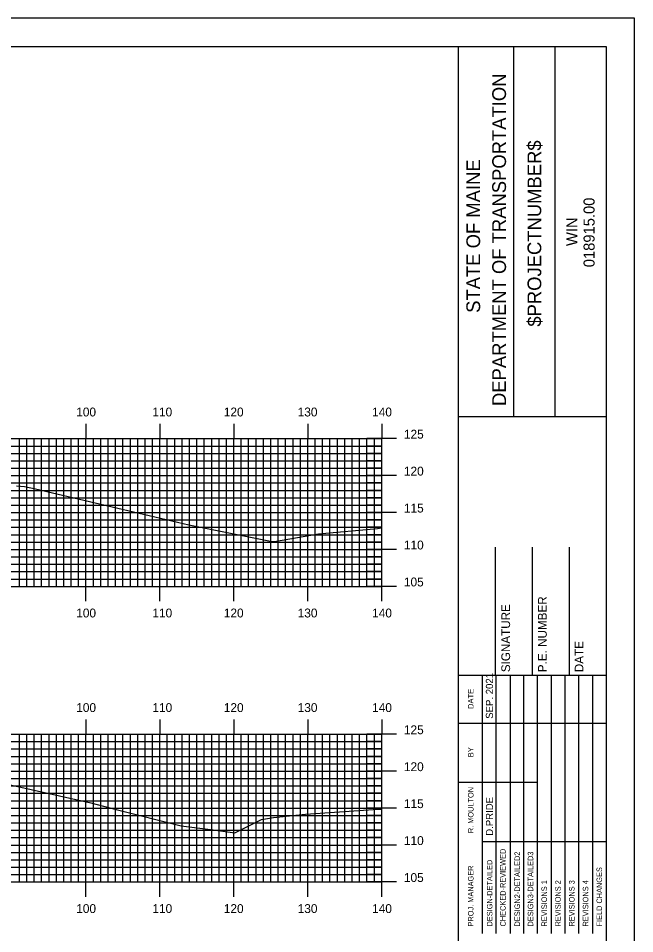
# Model space of a CAD drawing. Extents: x 855074 to 855418, y 366605 to 366825.
# Drawn here: x 855330.9 to 855414.3, y 366701.1 to 366824.9 of the extents above; entities that cross this region are included whole.
import ezdxf

# ---------------------------------------------------------------- set-up
doc = ezdxf.new("R2010")
doc.units = 0
for name, color, linetype in [('BORDER', 7, 'Continuous'), ('H_V ANNOTATION', 7, 'Continuous'), ('MAJOR', 7, 'Continuous'), ('MINOR', 7, 'Continuous'), ('PLOT BOUNDARY', 7, 'Continuous'), ('S_Roadway_Centerline', 7, 'Continuous')]:
    doc.layers.add(name, color=color, linetype=linetype)

msp = doc.modelspace()

# ---------------------------------------------------------------- linework, layer by layer
at = {"layer": 'BORDER'}
for p, q in [((855390.47, 366611.06), (855390.47, 366821.06)), ((855397.93, 366771.05), (855397.93, 366821.05)), ((855403.52, 366771.05), (855403.52, 366821.05)), ((855390.47, 366771.04), (855410.47, 366771.04)), ((855395.47, 366736.06), (855395.47, 366753.36)), ((855400.47, 366736.06), (855400.47, 366753.36)), ((855405.47, 366736.06), (855405.47, 366753.36)), ((855390.47, 366736.06), (855410.47, 366736.06))]:
    msp.add_line(p, q, dxfattribs=at)
msp.add_lwpolyline([(855090.47, 366611.06), (855410.47, 366611.06), (855410.47, 366821.06), (855090.47, 366821.06)], close=True, dxfattribs=at)
for points in [[(855393.7, 366729.56), (855393.7, 366736.06)], [(855395.56, 366701.07), (855395.56, 366736.06)], [(855397.43, 366736.06), (855397.43, 366701.07)], [(855399.29, 366701.07), (855399.29, 366736.06)], [(855401.15, 366701.07), (855401.15, 366736.06)], [(855403.02, 366701.07), (855403.02, 366736.06)], [(855404.88, 366701.07), (855404.88, 366736.06)], [(855406.74, 366701.07), (855406.74, 366736.06)], [(855408.61, 366701.07), (855408.61, 366736.06)], [(855393.7, 366701.07), (855393.7, 366734.65)], [(855390.47, 366729.56), (855410.47, 366729.56)], [(855390.47, 366721.56), (855393.7, 366721.56)], [(855393.7, 366721.56), (855401.15, 366721.56)], [(855393.7, 366713.56), (855410.47, 366713.56)]]:
    msp.add_lwpolyline(points, dxfattribs=at)
at = {"layer": 'MAJOR'}
for p, q in [((855340.07, 366770.06), (855340.07, 366768.06)), ((855350.07, 366770.06), (855350.07, 366768.06)), ((855360.07, 366770.06), (855360.07, 366768.06)), ((855370.07, 366770.06), (855370.07, 366768.06)), ((855380.07, 366770.06), (855380.07, 366768.06)), ((855100.07, 366768.06), (855380.07, 366768.06)), ((855100.07, 366768.06), (855380.07, 366768.06)), ((855340.07, 366748.06), (855340.07, 366768.06)), ((855350.07, 366748.06), (855350.07, 366768.06)), ((855360.07, 366748.06), (855360.07, 366768.06)), ((855370.07, 366748.06), (855370.07, 366768.06)), ((855382.07, 366768.06), (855378.07, 366768.06)), ((855380.07, 366748.06), (855380.07, 366768.06)), ((855380.07, 366748.06), (855380.07, 366768.06)), ((855100.07, 366763.06), (855380.07, 366763.06)), ((855382.07, 366763.06), (855378.07, 366763.06)), ((855100.07, 366758.06), (855380.07, 366758.06)), ((855382.07, 366758.06), (855378.07, 366758.06)), ((855100.07, 366753.06), (855380.07, 366753.06)), ((855382.07, 366753.06), (855378.07, 366753.06)), ((855100.07, 366748.06), (855380.07, 366748.06)), ((855100.07, 366748.06), (855380.07, 366748.06)), ((855340.07, 366746.05), (855340.07, 366748.06)), ((855350.07, 366746.05), (855350.07, 366748.06)), ((855360.07, 366746.05), (855360.07, 366748.06)), ((855370.07, 366746.05), (855370.07, 366748.06)), ((855382.07, 366748.06), (855378.07, 366748.06)), ((855380.07, 366746.05), (855380.07, 366748.06)), ((855340.07, 366730.06), (855340.07, 366728.06)), ((855350.07, 366730.06), (855350.07, 366728.06)), ((855360.07, 366730.06), (855360.07, 366728.06)), ((855370.07, 366730.06), (855370.07, 366728.06)), ((855380.07, 366730.06), (855380.07, 366728.06)), ((855100.07, 366728.06), (855380.07, 366728.06)), ((855100.07, 366728.06), (855380.07, 366728.06)), ((855340.07, 366708.06), (855340.07, 366728.06)), ((855350.07, 366708.06), (855350.07, 366728.06)), ((855360.07, 366708.06), (855360.07, 366728.06)), ((855370.07, 366708.06), (855370.07, 366728.06)), ((855382.07, 366728.06), (855378.07, 366728.06)), ((855380.07, 366708.06), (855380.07, 366728.06)), ((855380.07, 366708.06), (855380.07, 366728.06)), ((855100.07, 366723.06), (855380.07, 366723.06)), ((855382.07, 366723.06), (855378.07, 366723.06)), ((855100.07, 366718.06), (855380.07, 366718.06)), ((855382.07, 366718.06), (855378.07, 366718.06)), ((855100.07, 366713.06), (855380.07, 366713.06)), ((855382.07, 366713.06), (855378.07, 366713.06)), ((855100.07, 366708.06), (855380.07, 366708.06)), ((855100.07, 366708.06), (855380.07, 366708.06)), ((855340.07, 366706.05), (855340.07, 366708.06)), ((855350.07, 366706.05), (855350.07, 366708.06)), ((855360.07, 366706.05), (855360.07, 366708.06)), ((855370.07, 366706.05), (855370.07, 366708.06)), ((855382.07, 366708.06), (855378.07, 366708.06)), ((855380.07, 366706.05), (855380.07, 366708.06))]:
    msp.add_line(p, q, dxfattribs=at)
at = {"layer": 'MINOR'}
for p, q in [((855331.07, 366748.06), (855331.07, 366768.06)), ((855332.07, 366748.06), (855332.07, 366768.06)), ((855333.07, 366748.06), (855333.07, 366768.06)), ((855334.07, 366748.06), (855334.07, 366768.06)), ((855335.07, 366748.06), (855335.07, 366768.06)), ((855336.07, 366748.06), (855336.07, 366768.06)), ((855337.07, 366748.06), (855337.07, 366768.06)), ((855338.07, 366748.06), (855338.07, 366768.06)), ((855339.07, 366748.06), (855339.07, 366768.06)), ((855341.07, 366748.06), (855341.07, 366768.06)), ((855342.07, 366748.06), (855342.07, 366768.06)), ((855343.07, 366748.06), (855343.07, 366768.06)), ((855344.07, 366748.06), (855344.07, 366768.06)), ((855345.07, 366748.06), (855345.07, 366768.06)), ((855346.07, 366748.06), (855346.07, 366768.06)), ((855347.07, 366748.06), (855347.07, 366768.06)), ((855348.07, 366748.06), (855348.07, 366768.06)), ((855349.07, 366748.06), (855349.07, 366768.06)), ((855351.07, 366748.06), (855351.07, 366768.06)), ((855352.07, 366748.06), (855352.07, 366768.06)), ((855353.07, 366748.06), (855353.07, 366768.06)), ((855354.07, 366748.06), (855354.07, 366768.06)), ((855355.07, 366748.06), (855355.07, 366768.06)), ((855356.07, 366748.06), (855356.07, 366768.06)), ((855357.07, 366748.06), (855357.07, 366768.06)), ((855358.07, 366748.06), (855358.07, 366768.06)), ((855359.07, 366748.06), (855359.07, 366768.06)), ((855361.07, 366748.06), (855361.07, 366768.06)), ((855362.07, 366748.06), (855362.07, 366768.06)), ((855363.07, 366748.06), (855363.07, 366768.06)), ((855364.07, 366748.06), (855364.07, 366768.06)), ((855365.07, 366748.06), (855365.07, 366768.06)), ((855366.07, 366748.06), (855366.07, 366768.06)), ((855367.07, 366748.06), (855367.07, 366768.06)), ((855368.07, 366748.06), (855368.07, 366768.06)), ((855369.07, 366748.06), (855369.07, 366768.06)), ((855371.07, 366748.06), (855371.07, 366768.06)), ((855372.07, 366748.06), (855372.07, 366768.06)), ((855373.07, 366748.06), (855373.07, 366768.06)), ((855374.07, 366748.06), (855374.07, 366768.06)), ((855375.07, 366748.06), (855375.07, 366768.06)), ((855376.07, 366748.06), (855376.07, 366768.06)), ((855377.07, 366748.06), (855377.07, 366768.06)), ((855378.07, 366748.06), (855378.07, 366768.06)), ((855379.07, 366748.06), (855379.07, 366768.06)), ((855100.07, 366767.06), (855380.07, 366767.06)), ((855380.07, 366767.06), (855378.07, 366767.06)), ((855100.07, 366766.06), (855380.07, 366766.06)), ((855380.07, 366766.06), (855378.07, 366766.06)), ((855100.07, 366765.06), (855380.07, 366765.06)), ((855100.07, 366764.06), (855380.07, 366764.06)), ((855380.07, 366765.06), (855378.07, 366765.06)), ((855380.07, 366764.06), (855378.07, 366764.06)), ((855100.07, 366762.06), (855380.07, 366762.06)), ((855380.07, 366762.06), (855378.07, 366762.06)), ((855100.07, 366761.06), (855380.07, 366761.06)), ((855380.07, 366761.06), (855378.07, 366761.06)), ((855100.07, 366760.06), (855380.07, 366760.06)), ((855100.07, 366759.06), (855380.07, 366759.06)), ((855380.07, 366760.06), (855378.07, 366760.06)), ((855380.07, 366759.06), (855378.07, 366759.06)), ((855100.07, 366757.06), (855380.07, 366757.06)), ((855380.07, 366757.06), (855378.07, 366757.06)), ((855100.07, 366756.06), (855380.07, 366756.06)), ((855380.07, 366756.06), (855378.07, 366756.06)), ((855100.07, 366755.06), (855380.07, 366755.06)), ((855100.07, 366754.06), (855380.07, 366754.06)), ((855380.07, 366755.06), (855378.07, 366755.06)), ((855380.07, 366754.06), (855378.07, 366754.06)), ((855100.07, 366752.06), (855380.07, 366752.06)), ((855380.07, 366752.06), (855378.07, 366752.06)), ((855100.07, 366751.06), (855380.07, 366751.06)), ((855380.07, 366751.06), (855378.07, 366751.06)), ((855100.07, 366750.06), (855380.07, 366750.06)), ((855100.07, 366749.06), (855380.07, 366749.06)), ((855380.07, 366750.06), (855378.07, 366750.06)), ((855380.07, 366749.06), (855378.07, 366749.06)), ((855331.07, 366708.06), (855331.07, 366728.06)), ((855332.07, 366708.06), (855332.07, 366728.06)), ((855333.07, 366708.06), (855333.07, 366728.06)), ((855334.07, 366708.06), (855334.07, 366728.06)), ((855335.07, 366708.06), (855335.07, 366728.06)), ((855336.07, 366708.06), (855336.07, 366728.06)), ((855337.07, 366708.06), (855337.07, 366728.06)), ((855338.07, 366708.06), (855338.07, 366728.06)), ((855339.07, 366708.06), (855339.07, 366728.06)), ((855341.07, 366708.06), (855341.07, 366728.06)), ((855342.07, 366708.06), (855342.07, 366728.06)), ((855343.07, 366708.06), (855343.07, 366728.06)), ((855344.07, 366708.06), (855344.07, 366728.06)), ((855345.07, 366708.06), (855345.07, 366728.06)), ((855346.07, 366708.06), (855346.07, 366728.06)), ((855347.07, 366708.06), (855347.07, 366728.06)), ((855348.07, 366708.06), (855348.07, 366728.06)), ((855349.07, 366708.06), (855349.07, 366728.06)), ((855351.07, 366708.06), (855351.07, 366728.06)), ((855352.07, 366708.06), (855352.07, 366728.06)), ((855353.07, 366708.06), (855353.07, 366728.06)), ((855354.07, 366708.06), (855354.07, 366728.06)), ((855355.07, 366708.06), (855355.07, 366728.06)), ((855356.07, 366708.06), (855356.07, 366728.06)), ((855357.07, 366708.06), (855357.07, 366728.06)), ((855358.07, 366708.06), (855358.07, 366728.06)), ((855359.07, 366708.06), (855359.07, 366728.06)), ((855361.07, 366708.06), (855361.07, 366728.06)), ((855362.07, 366708.06), (855362.07, 366728.06)), ((855363.07, 366708.06), (855363.07, 366728.06)), ((855364.07, 366708.06), (855364.07, 366728.06)), ((855365.07, 366708.06), (855365.07, 366728.06)), ((855366.07, 366708.06), (855366.07, 366728.06)), ((855367.07, 366708.06), (855367.07, 366728.06)), ((855368.07, 366708.06), (855368.07, 366728.06)), ((855369.07, 366708.06), (855369.07, 366728.06)), ((855371.07, 366708.06), (855371.07, 366728.06)), ((855372.07, 366708.06), (855372.07, 366728.06)), ((855373.07, 366708.06), (855373.07, 366728.06)), ((855374.07, 366708.06), (855374.07, 366728.06)), ((855375.07, 366708.06), (855375.07, 366728.06)), ((855376.07, 366708.06), (855376.07, 366728.06)), ((855377.07, 366708.06), (855377.07, 366728.06)), ((855378.07, 366708.06), (855378.07, 366728.06)), ((855379.07, 366708.06), (855379.07, 366728.06)), ((855100.07, 366727.06), (855380.07, 366727.06)), ((855380.07, 366727.06), (855378.07, 366727.06)), ((855100.07, 366726.06), (855380.07, 366726.06)), ((855380.07, 366726.06), (855378.07, 366726.06)), ((855100.07, 366725.06), (855380.07, 366725.06)), ((855380.07, 366725.06), (855378.07, 366725.06)), ((855100.07, 366724.06), (855380.07, 366724.06)), ((855380.07, 366724.06), (855378.07, 366724.06)), ((855100.07, 366722.06), (855380.07, 366722.06)), ((855380.07, 366722.06), (855378.07, 366722.06)), ((855100.07, 366721.06), (855380.07, 366721.06)), ((855380.07, 366721.06), (855378.07, 366721.06)), ((855100.07, 366720.06), (855380.07, 366720.06)), ((855380.07, 366720.06), (855378.07, 366720.06)), ((855100.07, 366719.06), (855380.07, 366719.06)), ((855380.07, 366719.06), (855378.07, 366719.06)), ((855100.07, 366717.06), (855380.07, 366717.06)), ((855380.07, 366717.06), (855378.07, 366717.06)), ((855100.07, 366716.06), (855380.07, 366716.06)), ((855380.07, 366716.06), (855378.07, 366716.06)), ((855100.07, 366715.06), (855380.07, 366715.06)), ((855380.07, 366715.06), (855378.07, 366715.06)), ((855100.07, 366714.06), (855380.07, 366714.06)), ((855380.07, 366714.06), (855378.07, 366714.06)), ((855100.07, 366712.06), (855380.07, 366712.06)), ((855380.07, 366712.06), (855378.07, 366712.06)), ((855100.07, 366711.06), (855380.07, 366711.06)), ((855380.07, 366711.06), (855378.07, 366711.06)), ((855100.07, 366710.06), (855380.07, 366710.06)), ((855380.07, 366710.06), (855378.07, 366710.06)), ((855100.07, 366709.06), (855380.07, 366709.06)), ((855380.07, 366709.06), (855378.07, 366709.06))]:
    msp.add_line(p, q, dxfattribs=at)
at = {"layer": 'PLOT BOUNDARY'}
msp.add_lwpolyline([(855074.28, 366604.94), (855414.28, 366604.94), (855414.28, 366824.94), (855074.28, 366824.94)], close=True, dxfattribs=at)
at = {"layer": 'S_Roadway_Centerline'}
for points in [[(855330.67, 366761.65), (855331.75, 366761.59), (855333.23, 366761.28), (855349.39, 366757.48), (855353.98, 366756.39), (855365.24, 366754.13), (855365.36, 366754.12), (855365.82, 366754.18), (855371.5, 366755.16), (855379.52, 366755.9), (855380.07, 366755.97)], [(855328.37, 366721.53), (855340.72, 366718.76), (855344.14, 366717.87), (855352.96, 366715.67), (855357.25, 366715.13), (855360.22, 366714.72), (855363.82, 366716.5), (855365.41, 366716.77), (855369.74, 366717.25), (855379.61, 366717.9), (855380.07, 366717.91)]]:
    msp.add_lwpolyline(points, dxfattribs=at)

# ---------------------------------------------------------------- texts
at = {"layer": 'BORDER'}
for s, height, p in [('DEPARTMENT OF TRANSPORTATION', 1.8635, (855396.88, 366772.47)), ('$PROJECTNUMBER$', 1.8635, (855401.65, 366783.21)), ('STATE OF MAINE', 1.8635, (855393.38, 366785.08)), ('018915.00', 1.491, (855408.86, 366791.25)), ('WIN', 1.491, (855406.54, 366794.12)), ('P.E. NUMBER', 1.1811, (855402.39, 366736.45)), ('SIGNATURE', 1.181, (855397.43, 366736.45)), ('DATE', 1.181, (855407.35, 366736.45)), ('SEP. 2021', 0.969, (855395.12, 366730.15)), ('DATE', 0.743, (855392.48, 366731.47)), ('BY', 0.743, (855392.48, 366724.93)), ('R. MOULTON', 0.745, (855392.48, 366714.67)), ('D.PRIDE', 0.969, (855395.12, 366714.31)), ('CHECKED-REVIEWED', 0.7455, (855396.83, 366702.04)), ('DESIGN2-DETAILED2', 0.7455, (855398.77, 366702.04)), ('DESIGN3-DETAILED3', 0.7455, (855400.56, 366702.04)), ('DESIGN-DETAILED', 0.7455, (855395.04, 366702.04)), ('PROJ. MANAGER', 0.7455, (855392.48, 366702.04)), ('FIELD CHANGES', 0.7455, (855409.87, 366702.04)), ('REVISIONS 1', 0.7455, (855402.42, 366702.04)), ('REVISIONS 2', 0.7455, (855404.28, 366702.04)), ('REVISIONS 3', 0.7455, (855406.15, 366702.04)), ('REVISIONS 4', 0.7455, (855408.01, 366702.04))]:
    msp.add_text(s, height=height, rotation=90, dxfattribs=at).set_placement(p)
at = {"layer": 'H_V ANNOTATION'}
for s, p in [('100', (855338.75, 366771.06)), ('110', (855349.05, 366771.06)), ('120', (855358.71, 366771.06)), ('130', (855368.7, 366771.06)), ('140', (855378.77, 366771.06)), ('125', (855383.07, 366768.06)), ('120', (855383.07, 366763.06)), ('115', (855383.07, 366758.06)), ('110', (855383.07, 366753.06)), ('105', (855383.07, 366748.06)), ('100', (855338.75, 366743.86)), ('110', (855349.05, 366743.86)), ('120', (855358.71, 366743.86)), ('130', (855368.7, 366743.86)), ('140', (855378.77, 366743.86)), ('100', (855338.75, 366731.06)), ('110', (855349.05, 366731.06)), ('120', (855358.71, 366731.06)), ('130', (855368.7, 366731.06)), ('140', (855378.77, 366731.06)), ('125', (855383.07, 366728.06)), ('120', (855383.07, 366723.06)), ('115', (855383.07, 366718.06)), ('110', (855383.07, 366713.06)), ('105', (855383.07, 366708.06)), ('100', (855338.75, 366703.86)), ('110', (855349.05, 366703.86)), ('120', (855358.71, 366703.86)), ('130', (855368.7, 366703.86)), ('140', (855378.77, 366703.86))]:
    msp.add_text(s, height=1.2, dxfattribs=at).set_placement(p)

doc.saveas('drawing.dxf')
